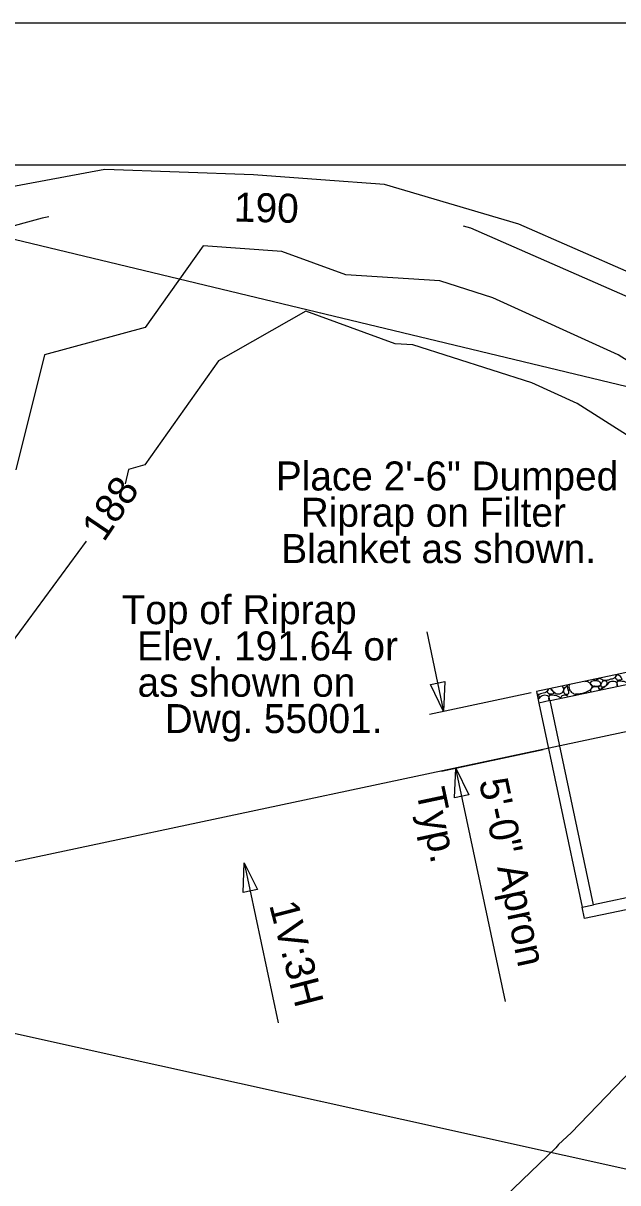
# Model space of a CAD drawing. Extents: x 1385284 to 1385995, y 1975154 to 1975620.
# Drawn here: x 1385397.4 to 1385448.7, y 1975519.6 to 1975619.6 of the extents above; entities that cross this region are included whole.
import ezdxf

# ---------------------------------------------------------------- set-up
doc = ezdxf.new("R2010")
doc.units = 0
for name, color, linetype in [('1', 7, 'Continuous'), ('Default', 7, 'Continuous'), ('DTM CONTOURS_MAJOR', 7, 'Continuous'), ('DTM_CONTOURS_MINOR', 7, 'Continuous'), ('R_Horz Alg Annot', 7, 'Continuous'), ('R_Proposed Const Limits', 7, 'Continuous'), ('S_WATER_UTILITIES', 7, 'Continuous')]:
    doc.layers.add(name, color=color, linetype=linetype)

msp = doc.modelspace()

# ---------------------------------------------------------------- linework, layer by layer
at = {"layer": '1'}
msp.add_line((1385315.54, 1975607.406), (1385982.69, 1975607.406), dxfattribs=at)
for points in [[(1385994.751, 1975619.62), (1385283.842, 1975619.62), (1385283.842, 1975153.738), (1385994.751, 1975153.738)], [(1385315.54, 1975165.953), (1385315.54, 1975607.406), (1385810.692, 1975607.406), (1385810.692, 1975586.483), (1385892.572, 1975586.483), (1385892.572, 1975580.3), (1385982.69, 1975580.3), (1385982.69, 1975165.953)]]:
    msp.add_lwpolyline(points, close=True, dxfattribs=at)
at = {"layer": 'Default'}
for p, q in [((1385432.193, 1975567.133), (1385433.648, 1975560.286)), ((1385460.488, 1975565.989), (1385441.639, 1975561.983)), ((1385442.825, 1975561.213), (1385460.696, 1975565.011)), ((1385441.639, 1975561.983), (1385441.847, 1975561.005)), ((1385441.181, 1975561.887), (1385432.426, 1975560.027)), ((1385442.825, 1975561.213), (1385441.847, 1975561.005)), ((1385441.847, 1975561.005), (1385445.589, 1975543.399)), ((1385446.567, 1975543.606), (1385442.825, 1975561.213)), ((1385433.465, 1975555.135), (1385442.221, 1975556.995)), ((1385438.967, 1975535.259), (1385434.688, 1975555.396)), ((1385416.456, 1975547.233), (1385419.389, 1975533.434)), ((1385464.438, 1975547.405), (1385446.567, 1975543.606)), ((1385464.646, 1975546.426), (1385445.797, 1975542.42)), ((1385445.589, 1975543.399), (1385446.567, 1975543.606)), ((1385445.589, 1975543.399), (1385446.567, 1975543.606)), ((1385445.797, 1975542.42), (1385445.589, 1975543.399))]:
    msp.add_line(p, q, dxfattribs=at)
for points in [[(1385433.74, 1975562.862), (1385433.648, 1975560.286), (1385432.517, 1975562.602)], [(1385434.596, 1975552.82), (1385434.688, 1975555.396), (1385435.819, 1975553.08)], [(1385416.365, 1975544.657), (1385416.456, 1975547.233), (1385417.588, 1975544.917)]]:
    msp.add_lwpolyline(points, close=True, dxfattribs=at)
for points in [[(1385446.757, 1975562.957), (1385446.687, 1975562.967), (1385446.617, 1975562.995), (1385446.547, 1975563.027)], [(1385447.074, 1975563.139), (1385447.07, 1975563.131), (1385447.019, 1975563.078), (1385446.909, 1975563.029), (1385446.806, 1975562.981), (1385446.757, 1975562.957)], [(1385447.481, 1975562.957), (1385447.409, 1975562.952), (1385447.283, 1975563.026), (1385447.132, 1975563.093), (1385447.097, 1975563.144)], [(1385448.614, 1975563.466), (1385448.583, 1975563.383), (1385448.453, 1975563.254), (1385448.239, 1975563.04), (1385447.962, 1975563.073), (1385447.726, 1975562.897), (1385447.56, 1975562.977), (1385447.481, 1975562.957)], [(1385448.707, 1975562.957), (1385448.66, 1975562.956), (1385448.564, 1975563.029), (1385448.401, 1975563.122), (1385448.51, 1975563.307), (1385448.558, 1975563.472), (1385448.739, 1975563.446), (1385448.859, 1975563.341), (1385448.926, 1975563.197), (1385449.113, 1975562.948), (1385448.363, 1975562.965), (1385448.749, 1975562.955), (1385448.741, 1975562.957)], [(1385442.721, 1975562.214), (1385442.686, 1975562.152), (1385442.571, 1975562.037), (1385442.369, 1975561.837), (1385442.093, 1975561.87), (1385441.877, 1975561.718), (1385441.746, 1975561.753), (1385441.687, 1975561.758)], [(1385442.838, 1975561.754), (1385442.791, 1975561.753), (1385442.695, 1975561.826), (1385442.532, 1975561.919), (1385442.63, 1975562.085), (1385442.683, 1975562.173), (1385442.723, 1975562.214)], [(1385442.861, 1975562.243), (1385442.905, 1975562.217), (1385442.992, 1975562.13), (1385443.056, 1975561.994), (1385443.243, 1975561.745), (1385442.494, 1975561.762), (1385442.88, 1975561.752), (1385442.872, 1975561.754)], [(1385443.52, 1975561.754), (1385443.449, 1975561.751), (1385443.267, 1975561.835), (1385443.073, 1975562.014), (1385442.945, 1975562.16), (1385442.879, 1975562.247)], [(1385443.872, 1975562.458), (1385443.919, 1975562.382), (1385443.996, 1975562.249), (1385443.959, 1975561.97), (1385443.773, 1975561.797), (1385443.605, 1975561.753), (1385443.52, 1975561.754)], [(1385444.098, 1975562.328), (1385444.067, 1975562.254), (1385443.929, 1975562.372), (1385443.87, 1975562.45), (1385443.865, 1975562.457)], [(1385444.424, 1975561.859), (1385444.414, 1975561.834), (1385444.366, 1975561.744), (1385444.243, 1975561.759), (1385444.065, 1975561.778), (1385444.027, 1975561.894), (1385443.953, 1975562.003), (1385443.992, 1975562.167), (1385444.086, 1975562.278), (1385444.163, 1975562.367), (1385444.243, 1975562.423), (1385444.368, 1975562.372), (1385444.325, 1975562.255), (1385444.387, 1975562.129), (1385444.469, 1975561.993), (1385444.406, 1975561.889), (1385444.424, 1975561.859)], [(1385444.336, 1975562.557), (1385444.293, 1975562.484), (1385444.218, 1975562.381), (1385444.124, 1975562.338), (1385444.098, 1975562.328)], [(1385445.025, 1975561.758), (1385444.957, 1975561.723), (1385444.734, 1975561.861), (1385444.519, 1975562.106), (1385444.434, 1975562.455), (1385444.532, 1975562.595), (1385444.535, 1975562.599)], [(1385445.817, 1975562.871), (1385445.878, 1975562.874), (1385446.045, 1975562.91), (1385446.232, 1975562.724), (1385446.484, 1975562.52), (1385446.359, 1975562.159), (1385446.07, 1975561.969), (1385445.702, 1975561.869), (1385445.33, 1975561.74), (1385445.097, 1975561.755), (1385445.025, 1975561.758)], [(1385446.652, 1975562.474), (1385446.597, 1975562.45), (1385446.452, 1975562.508), (1385446.29, 1975562.594), (1385446.28, 1975562.761), (1385446.357, 1975562.892), (1385446.576, 1975562.911), (1385446.876, 1975562.941), (1385447.174, 1975562.818), (1385447.234, 1975562.632), (1385447.138, 1975562.466), (1385446.932, 1975562.473), (1385446.772, 1975562.468), (1385446.652, 1975562.474)], [(1385446.344, 1975561.961), (1385446.316, 1975562.009), (1385446.324, 1975562.142), (1385446.431, 1975562.378), (1385446.646, 1975562.427), (1385447.008, 1975562.457), (1385447.02, 1975562.258), (1385447.06, 1975562.139), (1385447.068, 1975562.115)], [(1385447.196, 1975562.208), (1385447.159, 1975562.208), (1385447.074, 1975562.206), (1385446.994, 1975562.287), (1385447.003, 1975562.405), (1385447.087, 1975562.507), (1385447.214, 1975562.457), (1385447.317, 1975562.297), (1385447.23, 1975562.237), (1385447.196, 1975562.208)], [(1385447.143, 1975562.131), (1385447.157, 1975562.159), (1385447.23, 1975562.274), (1385447.432, 1975562.318), (1385447.632, 1975562.477), (1385447.812, 1975562.619), (1385447.906, 1975562.825), (1385448.118, 1975562.918), (1385448.333, 1975562.892), (1385448.596, 1975562.806), (1385448.586, 1975562.625), (1385448.618, 1975562.492), (1385448.625, 1975562.446)], [(1385447.624, 1975562.474), (1385447.576, 1975562.459), (1385447.48, 1975562.436), (1385447.345, 1975562.382), (1385447.219, 1975562.424), (1385447.192, 1975562.53), (1385447.222, 1975562.644), (1385447.265, 1975562.771), (1385447.326, 1975562.896), (1385447.476, 1975562.912), (1385447.648, 1975562.908), (1385447.761, 1975562.781), (1385447.737, 1975562.621), (1385447.676, 1975562.504), (1385447.624, 1975562.474)], [(1385448.631, 1975562.447), (1385448.621, 1975562.472), (1385448.578, 1975562.559), (1385448.603, 1975562.707), (1385448.673, 1975562.949), (1385448.902, 1975562.897), (1385449.172, 1975562.902), (1385449.413, 1975562.78), (1385449.534, 1975562.691), (1385449.58, 1975562.649)], [(1385441.699, 1975561.699), (1385441.73, 1975561.694), (1385441.806, 1975561.674), (1385441.892, 1975561.578), (1385441.872, 1975561.429), (1385441.82, 1975561.326), (1385441.785, 1975561.294)], [(1385441.784, 1975561.299), (1385441.836, 1975561.349), (1385441.948, 1975561.428), (1385442.037, 1975561.622), (1385442.249, 1975561.715), (1385442.464, 1975561.689), (1385442.727, 1975561.603), (1385442.717, 1975561.409), (1385442.756, 1975561.26), (1385442.761, 1975561.2)], [(1385442.781, 1975561.204), (1385442.762, 1975561.241), (1385442.707, 1975561.34), (1385442.733, 1975561.504), (1385442.804, 1975561.746), (1385443.033, 1975561.694), (1385443.303, 1975561.699), (1385443.562, 1975561.569), (1385443.691, 1975561.468), (1385443.749, 1975561.41)], [(1385443.783, 1975561.417), (1385443.78, 1975561.428), (1385443.767, 1975561.484), (1385443.811, 1975561.631), (1385443.975, 1975561.703), (1385444.202, 1975561.711), (1385444.325, 1975561.614), (1385444.36, 1975561.547), (1385444.363, 1975561.54)], [(1385444.834, 1975561.64), (1385444.862, 1975561.652), (1385444.956, 1975561.68), (1385445.052, 1975561.696), (1385445.117, 1975561.7)]]:
    msp.add_open_spline(points, degree=3, dxfattribs=at)
at = {"layer": 'DTM CONTOURS_MAJOR'}
for points in [[(1385399.624, 1975602.925), (1385399.045, 1975602.817), (1385391.963, 1975600.882), (1385387.453, 1975582.667), (1385384.307, 1975576.794), (1385382.281, 1975574.037), (1385379.687, 1975572.814), (1385367.751, 1975562.197), (1385367.144, 1975561.895), (1385358.794, 1975555.313), (1385352.954, 1975551.793), (1385352.888, 1975550.538), (1385339.434, 1975539.661), (1385338.494, 1975538.243), (1385335.028, 1975533.358)], [(1385522.056, 1975554.091), (1385511.021, 1975558.588), (1385498.653, 1975563.634), (1385496.045, 1975565.603), (1385483.372, 1975575.846), (1385482.113, 1975576.798), (1385470.917, 1975585.913), (1385468.561, 1975587.657), (1385452.473, 1975594.716), (1385451.663, 1975595.064), (1385435.988, 1975601.935), (1385435.363, 1975602.12)]]:
    msp.add_lwpolyline(points, dxfattribs=at)
at = {"layer": 'DTM_CONTOURS_MINOR'}
for points in [[(1385514.589, 1975561.539), (1385512.543, 1975562.616), (1385501.115, 1975567.556), (1385496.853, 1975569.996), (1385485.373, 1975578.699), (1385479.845, 1975581.695), (1385469.098, 1975589.652), (1385457.886, 1975594.571), (1385449.838, 1975598.029), (1385440.126, 1975602.287), (1385428.54, 1975605.711), (1385423.05, 1975606.119), (1385417.264, 1975606.549), (1385404.449, 1975607.001), (1385394.252, 1975605.116), (1385386.475, 1975604.033), (1385375.432, 1975601.945), (1385366.349, 1975599.957), (1385356.912, 1975595.013), (1385349.735, 1975591.254), (1385341.987, 1975580.912), (1385341.879, 1975572.907)], [(1385488.189, 1975564.366), (1385483.74, 1975567.963), (1385474.707, 1975574.791), (1385467.529, 1975580.634), (1385462.767, 1975583.789), (1385453.007, 1975588.282), (1385448.704, 1975591.02), (1385437.889, 1975595.952), (1385433.309, 1975597.404), (1385425.221, 1975597.918), (1385419.709, 1975599.94), (1385412.905, 1975600.422), (1385407.929, 1975593.394), (1385399.227, 1975591.016), (1385396.775, 1975581.115)], [(1385534.545, 1975545.92), (1385529.729, 1975545.685), (1385519.689, 1975538.171), (1385502.211, 1975546.507), (1385502.041, 1975546.577), (1385501.882, 1975546.641), (1385484.577, 1975559.699), (1385484.107, 1975560.079), (1385467.301, 1975572.783), (1385466.481, 1975573.451), (1385456.805, 1975579.862), (1385454.291, 1975581.019), (1385445.143, 1975586.839), (1385441.234, 1975588.622), (1385430.98, 1975591.874), (1385429.467, 1975591.97), (1385421.762, 1975594.796), (1385414.234, 1975590.496), (1385407.886, 1975581.531), (1385406.491, 1975581.15), (1385406.184, 1975579.91)], [(1385402.827, 1975574.972), (1385394.912, 1975564.202), (1385380.94, 1975557.613), (1385377.739, 1975554.766), (1385365.573, 1975548.728), (1385361.059, 1975545.17), (1385355.99, 1975541.174), (1385343.152, 1975530.795), (1385341.606, 1975528.616), (1385334.486, 1975514.442), (1385346.452, 1975516.912), (1385359.805, 1975514.637), (1385370.641, 1975499.323)], [(1385519.816, 1975518.527), (1385513.167, 1975531.095), (1385503.103, 1975535.092), (1385493.819, 1975536.129), (1385487.034, 1975541.44), (1385476.692, 1975537.174), (1385462.514, 1975531.326), (1385459.65, 1975533.856), (1385457.485, 1975537.268), (1385444.649, 1975523.958), (1385443.539, 1975522.941), (1385443.305, 1975522.664), (1385433.898, 1975513.612), (1385427.6, 1975506.926)]]:
    msp.add_lwpolyline(points, dxfattribs=at)
at = {"layer": 'R_Horz Alg Annot'}
msp.add_line((1385315.54, 1975550.51), (1385664.693, 1975473.094), dxfattribs=at)
at = {"layer": 'R_Proposed Const Limits'}
msp.add_lwpolyline([(1385461.528, 1975561.099), (1385340.372, 1975535.35)], dxfattribs=at)
at = {"layer": 'S_WATER_UTILITIES'}
msp.add_line((1385373.628, 1975606.526), (1385516.104, 1975572.278), dxfattribs=at)

# ---------------------------------------------------------------- texts
at = {"layer": 'Default'}
for s, height, rotation, p in [('190', 2.5, 358.71041, (1385415.553, 1975602.52)), ('188', 2.5, 55.79183, (1385404.358, 1975574.805)), ('5\'-0" Apron', 2.49999, 281.99838, (1385436.676, 1975554.263)), ('Typ.', 2.5, 281.99838, (1385431.255, 1975553.417)), ('1V:3H', 2.5, 284.53968, (1385418.591, 1975543.597))]:
    msp.add_text(s, height=height, rotation=rotation, dxfattribs=at).set_placement(p)
for s, p in [('Place 2\'-6" Dumped ', (1385419.181, 1975579.33)), ('Riprap on Filter ', (1385421.33, 1975576.2)), ('Blanket as shown.', (1385419.653, 1975573.07)), ('Top of Riprap', (1385405.894, 1975567.803)), ('Elev. 191.64 or ', (1385407.216, 1975564.674)), ('as shown on ', (1385407.264, 1975561.544)), ('Dwg. 55001.', (1385409.602, 1975558.414))]:
    msp.add_text(s, height=2.49999, dxfattribs=at).set_placement(p)

doc.saveas('drawing.dxf')
